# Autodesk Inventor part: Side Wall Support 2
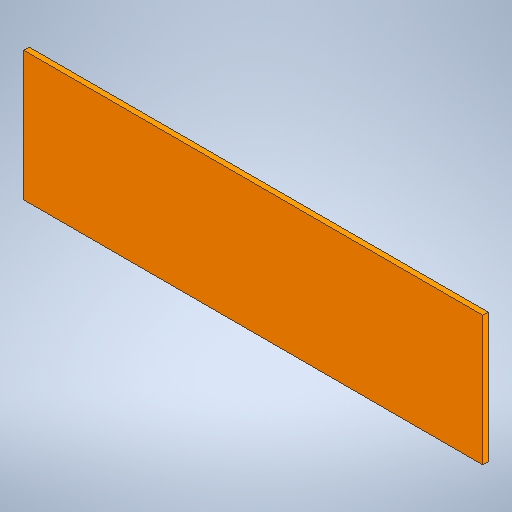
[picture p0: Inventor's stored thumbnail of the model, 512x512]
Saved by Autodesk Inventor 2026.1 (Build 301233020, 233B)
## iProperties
Created: 2026-11
Part Number: Side Wall Support 2
Material: Generic
Document SubType Name: Modeling
Designer: hp
Density: 1 g/cm^3
Appearance: Default
Author: hp
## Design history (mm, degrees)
sketch "Sketch1"
  geometry: L1 (0, 0)-(425, 0); L2 (425, 0)-(425, 120); L3 (425, 120)-(0, 120); L4 (0, 120)-(0, 0)
  constraints: 8 end point, 2 parallel, 1 horizontal, 1 perpendicular
  dimensions: "d0" = 425 distance of L3.end L2.end; "d1" = 120 distance of L2.end L1.end
extrude "Extrusion1" new body sketch "Sketch1" distance "d2" = 5; taper "d3" = 0 deg
body "Solid1"
